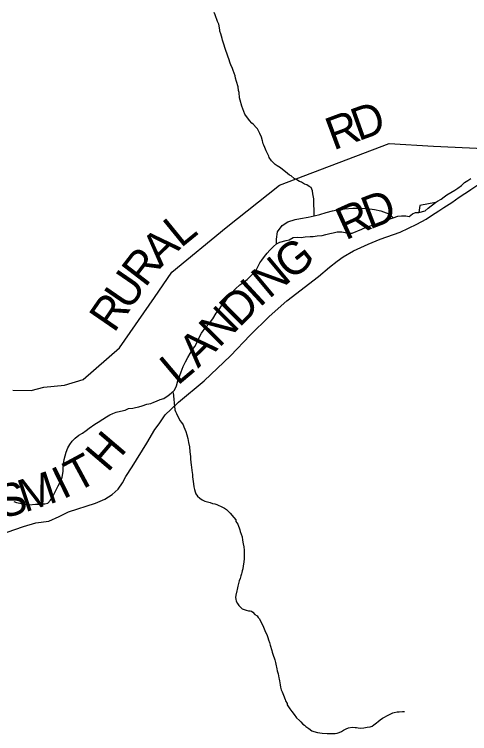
# Model space of a CAD drawing. Extents: x 1310247 to 1664935, y 235267 to 584339.
# Drawn here: x 1519987 to 1524176, y 290011 to 296629 of the extents above; entities that cross this region are included whole.
import ezdxf

# ---------------------------------------------------------------- set-up
doc = ezdxf.new("R2010")
doc.units = 0
for name, color, linetype in [('GM_X_County_Road', 7, 'Continuous'), ('GM_X_County_Road_Text', 7, 'Continuous'), ('GM_X_Minor_River', 7, 'Continuous'), ('GM_X_Township_Road', 7, 'Continuous'), ('GM_X_Township_Road_Text', 7, 'Continuous')]:
    doc.layers.add(name, color=color, linetype=linetype)

msp = doc.modelspace()

# ---------------------------------------------------------------- linework, layer by layer
at = {"layer": 'GM_X_County_Road'}
msp.add_lwpolyline([(1519974, 293171.2), (1520141.6, 293169.6), (1520257.7, 293197.6), (1520447.3, 293218.2), (1520621.1, 293270.8), (1520955.4, 293559.6), (1521274.7, 294022.9), (1521436.4, 294256.6), (1521937, 294668.8), (1522427.6, 295058.7), (1523436.7, 295441.4), (1523844.9, 295415.5), (1524305.3, 295395.9)], dxfattribs=at)
at = {"layer": 'GM_X_Minor_River'}
for points in [[(1522745.7, 294775.5), (1522743.4, 294933.1), (1522733.9, 294977.4), (1522730.2, 295005.6), (1522724.3, 295021.7), (1522716.5, 295035.8), (1522698.5, 295044.1), (1522676.6, 295060.5), (1522656.6, 295066.7), (1522628.7, 295085.1), (1522610.7, 295091.4), (1522576.8, 295113.9), (1522560.8, 295120.1), (1522535, 295142.5), (1522517, 295150.8), (1522483.2, 295179.3), (1522469.3, 295189.5), (1522435.5, 295216.1), (1522403.6, 295236.6), (1522387.7, 295248.8), (1522365.8, 295269.1), (1522353.9, 295281.3), (1522332.2, 295311.7), (1522328.3, 295323.8), (1522310.7, 295360.2), (1522304.8, 295374.3), (1522291.1, 295404.6), (1522281.3, 295426.8), (1522275.5, 295438.9), (1522273.6, 295453), (1522269.7, 295465.1), (1522260.1, 295499.3), (1522246.4, 295531.6), (1522240.6, 295543.8), (1522222.9, 295576.1), (1522213, 295588.3), (1522187.2, 295616.7), (1522173.3, 295628.9), (1522149.5, 295653.3), (1522108, 295710.1), (1522088.5, 295760.5), (1522078.8, 295784.7), (1522065.4, 295841.1), (1522059.6, 295861.2), (1522054.2, 295911.5), (1522050.4, 295929.6), (1522044.7, 295963.8), (1522031.3, 296012.2), (1522021.6, 296042.4), (1522017.8, 296064.5), (1522000.3, 296112.9), (1521992.5, 296131.1), (1521978.9, 296165.4), (1521973, 296179.5), (1521959.4, 296219.8), (1521953.6, 296236), (1521942, 296272.2), (1521936.1, 296286.4), (1521924.5, 296324.7), (1521916.8, 296346.8), (1521903.3, 296393.2), (1521897.4, 296407.3), (1521887.9, 296449.6), (1521878.2, 296475.8), (1521876.3, 296487.9), (1521866.8, 296538.2), (1521857.1, 296564.4), (1521835.7, 296624.9), (1521826, 296647.1)], [(1523861.4, 294896.8), (1523881.9, 294910.7), (1523914.3, 294928.1), (1523940.8, 294949.7), (1523967.2, 294967.2), (1524040.2, 295010), (1524068.7, 295029.5), (1524101.3, 295054.9), (1524129.9, 295082.5), (1524160.3, 295099.9), (1524186.7, 295119.5)], [(1523861.4, 294896.8), (1523718.1, 294869.5), (1523708.8, 294805.4)], [(1523708.8, 294805.4), (1523765.4, 294822.4), (1523796, 294845.9), (1523861.4, 294896.8)], [(1522399.9, 294517.6), (1522397.9, 294559.3), (1522409.2, 294627.3), (1522450.6, 294686.7), (1522503.5, 294719.8), (1522570.2, 294742.6), (1522620.6, 294749.7), (1522691.2, 294764.4), (1522745.7, 294775.5), (1522796.2, 294788.5), (1522856.8, 294807.5), (1522913.4, 294822.4), (1522971.9, 294833.4), (1523024.2, 294840.4), (1523102.7, 294845), (1523157, 294845.9), (1523233.3, 294842.5), (1523301.4, 294833.2), (1523357.4, 294820.1), (1523431.3, 294792.6), (1523471.7, 294756)], [(1522625.7, 294575.5), (1522663.9, 294580.8), (1522708.1, 294584), (1522736.2, 294585.5), (1522774.5, 294590.8), (1522818.7, 294595.9), (1522852.9, 294603.3), (1522889.2, 294612.7), (1522921.5, 294620.1), (1522957.8, 294629.4), (1522999.8, 294626.6), (1523031.9, 294622), (1523065.9, 294617.3), (1523093.9, 294614.8), (1523182.9, 294651.2), (1523225.4, 294672.5), (1523273.8, 294687.6), (1523304.1, 294697), (1523346.6, 294714.3), (1523372.7, 294719.8), (1523403.2, 294737.3), (1523435.4, 294744.7), (1523471.7, 294756), (1523516.2, 294773.2), (1523550.3, 294774.6), (1523590.5, 294775.9), (1523618.4, 294769.3), (1523651, 294792.8), (1523679.3, 294806.3), (1523708.8, 294805.4)], [(1519980.3, 292147.6), (1520006.2, 292139.1), (1520036.2, 292132.5), (1520070.2, 292123.8), (1520122.2, 292114.8), (1520182.5, 292121.7), (1520208.6, 292121.2), (1520238.8, 292126.7), (1520266.8, 292126.1), (1520295, 292131.6), (1520319.6, 292159.2), (1520336.2, 292187), (1520356.9, 292224.7), (1520375.7, 292260.4), (1520390.3, 292290.2), (1520413.2, 292337.9), (1520425.8, 292369.7), (1520434.8, 292421.7), (1520435.3, 292447.7), (1520440.2, 292493.8), (1520444.9, 292533.8), (1520453.6, 292565.7), (1520464.3, 292601.6), (1520479, 292641.4), (1520497.6, 292671.1), (1520518.3, 292700.8), (1520546.9, 292728.3), (1520579.5, 292755.8), (1520613.9, 292775.2), (1520648.5, 292798.6), (1520675, 292822.1), (1520725.9, 292859.3), (1520756.3, 292876.7), (1520800.9, 292904), (1520835.4, 292925.3), (1520865.9, 292942.8), (1520892.2, 292956.4), (1520922.5, 292967.8), (1520964.8, 292977), (1521005.1, 292988.3), (1521037.5, 293001.7), (1521075.7, 293007), (1521101.9, 293012.5), (1521132.1, 293018), (1521162.4, 293027.4), (1521204.8, 293042.7), (1521241, 293048), (1521269.3, 293059.5), (1521295.6, 293069), (1521327.9, 293084.5), (1521362.2, 293093.8), (1521400.9, 293121.2), (1521429.3, 293142.7), (1521459.9, 293170.2), (1521478.7, 293209.9), (1521491.7, 293257.8), (1521521.3, 293341.4), (1521540.3, 293389.2), (1521561.1, 293432.9), (1521581.9, 293470.6), (1521604.7, 293508.2), (1521627.4, 293543.9), (1521648, 293573.6), (1521668.8, 293613.3), (1521685.6, 293651.1), (1521708.5, 293694.7), (1521749.6, 293750.1), (1521782.4, 293787.6), (1521813.3, 293829.1), (1521844.3, 293878.6), (1521871, 293912.2), (1521893.7, 293947.8), (1521920.3, 293975.4), (1521941, 294007.1), (1521961.5, 294032.8), (1521986.2, 294062.4), (1522021, 294103.8), (1522061.8, 294139.1), (1522090.3, 294158.6), (1522129, 294190), (1522157.6, 294217.5), (1522186.2, 294249), (1522212.8, 294276.6), (1522227.4, 294306.4), (1522246.2, 294342.1), (1522262.7, 294367.9), (1522289.4, 294401.5), (1522314.1, 294433), (1522336.6, 294458.7), (1522371.3, 294492.1), (1522399.9, 294517.6), (1522428.3, 294533.1), (1522486.8, 294548.1), (1522515, 294555.6), (1522553.5, 294574.9), (1522589.7, 294580.2), (1522625.7, 294575.5)], [(1521447.5, 293150.5), (1521463.1, 292989.7), (1521469, 292975.5), (1521478.8, 292955.3), (1521508.1, 292890.7), (1521524, 292874.5), (1521539.8, 292852.2), (1521547.6, 292834), (1521563.2, 292789.6), (1521572.8, 292759.4), (1521582.5, 292727.1), (1521590.1, 292688.9), (1521597.6, 292648.6), (1521601.1, 292604.4), (1521606.6, 292560.1), (1521608.4, 292536), (1521613.7, 292481.7), (1521615.5, 292461.6), (1521621.2, 292431.4), (1521624.8, 292395.2), (1521626.5, 292373.1), (1521633.8, 292308.8), (1521637.5, 292282.6), (1521643.2, 292256.5), (1521649, 292234.3), (1521656.8, 292218.1), (1521672.6, 292195.8), (1521692.5, 292177.5), (1521714.4, 292161.2), (1521740.3, 292150.8), (1521764.3, 292142.5), (1521788.4, 292136.1), (1521810.4, 292129.8), (1521830.4, 292125.5), (1521850.4, 292119.3), (1521868.4, 292111), (1521884.4, 292102.8), (1521902.3, 292094.5), (1521920.3, 292084.2), (1521938.2, 292072), (1521954.1, 292057.7), (1521974, 292039.4), (1522005.7, 292000.8), (1522023.5, 291978.5), (1522025.3, 291962.4), (1522043.1, 291938.1), (1522060.5, 291885.6), (1522064.4, 291869.5), (1522074.1, 291845.3), (1522081.9, 291821.1), (1522087.5, 291790.9), (1522093.2, 291758.7), (1522098.8, 291728.5), (1522102.5, 291700.4), (1522102.2, 291674.2), (1522101.6, 291622), (1522099.2, 291587.9), (1522092.8, 291553.9), (1522088.4, 291527.8), (1522084.2, 291509.8), (1522080, 291493.8), (1522075.8, 291479.8), (1522069.6, 291461.8), (1522063.3, 291439.8), (1522055, 291415.8), (1522042.4, 291367.8), (1522036, 291335.7), (1522033.8, 291323.7), (1522025.3, 291285.6), (1522023, 291263.6), (1522024.9, 291249.5), (1522028.7, 291229.4), (1522040.5, 291207.1), (1522052.3, 291188.9), (1522066.2, 291174.7), (1522084.1, 291160.4), (1522102.1, 291152.1), (1522120.1, 291145.8), (1522140.1, 291141.6), (1522156.1, 291139.4), (1522168.2, 291137.2), (1522180.1, 291129), (1522199.9, 291106.7), (1522219.9, 291094.4), (1522229.7, 291078.2), (1522241.6, 291066), (1522251.4, 291045.8), (1522267.2, 291019.5), (1522278.9, 290989.2), (1522292.6, 290960.9), (1522312.1, 290912.5), (1522317.9, 290896.3), (1522325.7, 290874.1), (1522333.4, 290849.9), (1522341.2, 290823.7), (1522354.7, 290777.3), (1522358.5, 290761.2), (1522370.1, 290722.9)], [(1521362.2, 293093.8), (1521365, 293096)], [(1522370.1, 290722.9), (1522376, 290708.8), (1522383.8, 290688.6), (1522389.5, 290664.4), (1522391.3, 290650.3), (1522400.9, 290606), (1522404.7, 290589.9), (1522414.4, 290561.7), (1522418.2, 290543.6), (1522420, 290525.5), (1522423.8, 290511.4), (1522425.7, 290497.3), (1522429.5, 290477.1), (1522433.3, 290459), (1522437, 290436.9), (1522442.8, 290414.7), (1522450.6, 290396.5), (1522462.3, 290364.2), (1522477.8, 290323.9), (1522481.7, 290311.8), (1522495.5, 290289.5), (1522497.4, 290275.4), (1522521, 290239), (1522540.8, 290214.6), (1522560.6, 290188.3), (1522582.3, 290155.8), (1522610.1, 290131.4), (1522622, 290119.2), (1522641.9, 290098.8), (1522655.8, 290088.6), (1522669.7, 290076.4), (1522697.6, 290058), (1522725.5, 290037.5), (1522741.5, 290031.3), (1522775.5, 290022.8), (1522819.6, 290016.2), (1522863.8, 290011.7), (1522911.9, 290011), (1522938.1, 290012.7), (1522958.2, 290016.5), (1522976.3, 290020.3), (1522998.5, 290032), (1523014.7, 290041.9), (1523028.9, 290047.7), (1523041, 290053.6), (1523061.2, 290065.4), (1523095.4, 290069), (1523121.5, 290068.6), (1523133.5, 290066.5), (1523151.5, 290064.2), (1523173.6, 290061.9), (1523201.7, 290063.6), (1523233.9, 290069.2), (1523260.1, 290074.9), (1523280.3, 290080.7), (1523294.4, 290090.5), (1523318.8, 290110.3), (1523333, 290122.2), (1523353.2, 290138), (1523373.5, 290151.8), (1523391.7, 290163.6), (1523413.9, 290175.4), (1523426, 290181.2), (1523440.2, 290187.1), (1523456.3, 290196.9), (1523470.5, 290200.8), (1523482.6, 290206.6), (1523508.7, 290212.3), (1523526.8, 290212.1), (1523557, 290213.7), (1523577, 290213.5)]]:
    msp.add_lwpolyline(points, dxfattribs=at)
at = {"layer": 'GM_X_Township_Road'}
for points in [[(1524175.9, 295009.7), (1524188.1, 295017.6), (1524242.9, 295054.4), (1524280.9, 295076.6), (1524311.1, 295099), (1524333.4, 295127.9), (1524391.2, 295226.1), (1524447.9, 295323.8), (1524497.9, 295407.5), (1524613, 295513.6)], [(1521495.8, 293059.6), (1521734.5, 293256.5), (1521975, 293488.5), (1522157, 293676), (1522330.6, 293850.1), (1522495.2, 293992.3), (1522784, 294215.6), (1522885.7, 294304), (1522958.6, 294358.8), (1523013.4, 294396.8), (1523107.5, 294452.9), (1523243, 294515.5), (1523351.5, 294561.4), (1523537.2, 294626.4), (1523689.7, 294697.5), (1523775.9, 294744), (1523825.9, 294778.3), (1523893.4, 294822.3), (1523939.8, 294850.6), (1524012.1, 294898.9), (1524079.6, 294946.5), (1524132.1, 294981.4), (1524175.9, 295009.7)], [(1519709.4, 291826.3), (1519764.2, 291822), (1519845.6, 291840.7), (1520071.6, 291916.6), (1520185.5, 291949.8), (1520304.2, 291966.7), (1520398.3, 292008.3), (1520485.1, 292051.6), (1520734, 292131.8), (1520819.6, 292169.2), (1520885.9, 292212.6), (1520943.1, 292260.8), (1520981.1, 292317.5), (1521013.7, 292377.7), (1521071.5, 292465.1), (1521205.3, 292683.3), (1521279.4, 292809.3), (1521319.8, 292860.5), (1521375.3, 292943), (1521429.2, 292997.9), (1521494.5, 293058.5), (1521495.8, 293059.6)]]:
    msp.add_lwpolyline(points, dxfattribs=at)

# ---------------------------------------------------------------- texts
at = {"layer": 'GM_X_County_Road_Text'}
for s, rotation, p in [('D', 19.65554, (1523152.5, 295461.7)), ('R', 20.49529, (1522922.8, 295375.8)), ('L', 39.17535, (1521518.1, 294474.1)), ('A', 44.12226, (1521333.7, 294294.8)), ('R', 52.44413, (1521191.1, 294108.1)), ('U', 55.46882, (1521043.9, 293894)), ('R', 55.48991, (1520904.4, 293691))]:
    msp.add_text(s, height=300, rotation=rotation, dxfattribs=at).set_placement(p)
at = {"layer": 'GM_X_Township_Road_Text'}
for s, rotation, p in [('D', 21.00756, (1523254.1, 294647.4)), ('R', 24.35214, (1523033.9, 294547.6)), ('G', 38.45102, (1522530.6, 294173.5)), ('N', 39.83355, (1522329.3, 294005.6)), ('I', 42.76409, (1522241.9, 293924.6)), ('D', 44.66965, (1522056.1, 293740.8)), ('N', 45.00211, (1521869.8, 293554.5)), ('A', 44.15805, (1521676.9, 293367.2)), ('L', 40.14934, (1521488.4, 293207.1)), ('H', 49.55638, (1520846, 292406.2)), ('T', 28.37918, (1520555, 292223.9)), ('I', 26.0933, (1520432.7, 292163.7)), ('M', 18.31564, (1520082.5, 292044.6)), ('S', 14.82682, (1519867.7, 291987.1))]:
    msp.add_text(s, height=300, rotation=rotation, dxfattribs=at).set_placement(p)

doc.saveas('drawing.dxf')
